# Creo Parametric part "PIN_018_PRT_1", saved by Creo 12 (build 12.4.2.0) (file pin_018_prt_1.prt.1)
Units: Custom; MM, KILOGRAM, SECS

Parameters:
  PTC_WM_ITERATION = "0"
  PTC_WM_VERSION = "-.0"
  PTC_WM_LIFECYCLE_STATE = "In Work"
  PTC_WM_LIFECYCLE = "MO_CADDocument"
  PTC_WM_CREATED_BY = "Maximilian Roepper (Z0017RMS: MO)"
  PTC_WM_CREATED_ON = "18-Sep-26 11:36:42 AM"
  PTC_WM_MODIFIED_BY = "Maximilian Roepper (Z0017RMS: MO)"
  PTC_WM_MODIFIED_ON = "18-Sep-26 11:36:46 AM"
  PDMLINKNUMBER = "PDM000071455023"
  PTC_WM_NAME = "pin_018_prt_1.prt"
  PTC_WM_NUMBER = "PDM000071455023"

Other parameters: WEIGHT, WEIGHT_FACTOR, WEIGHT_ADD, _MASS_TEMP, _DIFF_TEMP, MC_ERRORS, SUPPLIER

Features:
  1. coordinate system
  2. datum plane "PRT_YZ"
  3. datum plane "PRT_XY"
  4. datum plane "PRT_XZ"
  5. coordinate system
  6. datum axis
  7. datum axis
  8. datum axis
  9. coordinate system
  10. imported feature
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
Other named items: PRT, SIEMENS_MO, DRW_VIEW_ORG, PRT_X, PRT_Y, PRT_Z, CS0, ROUGH_GROB

Layers: 00_STD_CSYS-KSYS, 01_STD_PLANES-EBENEN, 02_STD_AXES-ACHSEN, 03_STD_CSYS-KSYS, 24_IMPORT_FEAT-IMPORT_KE

Surfaces: 9 plane, 1 cylinder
